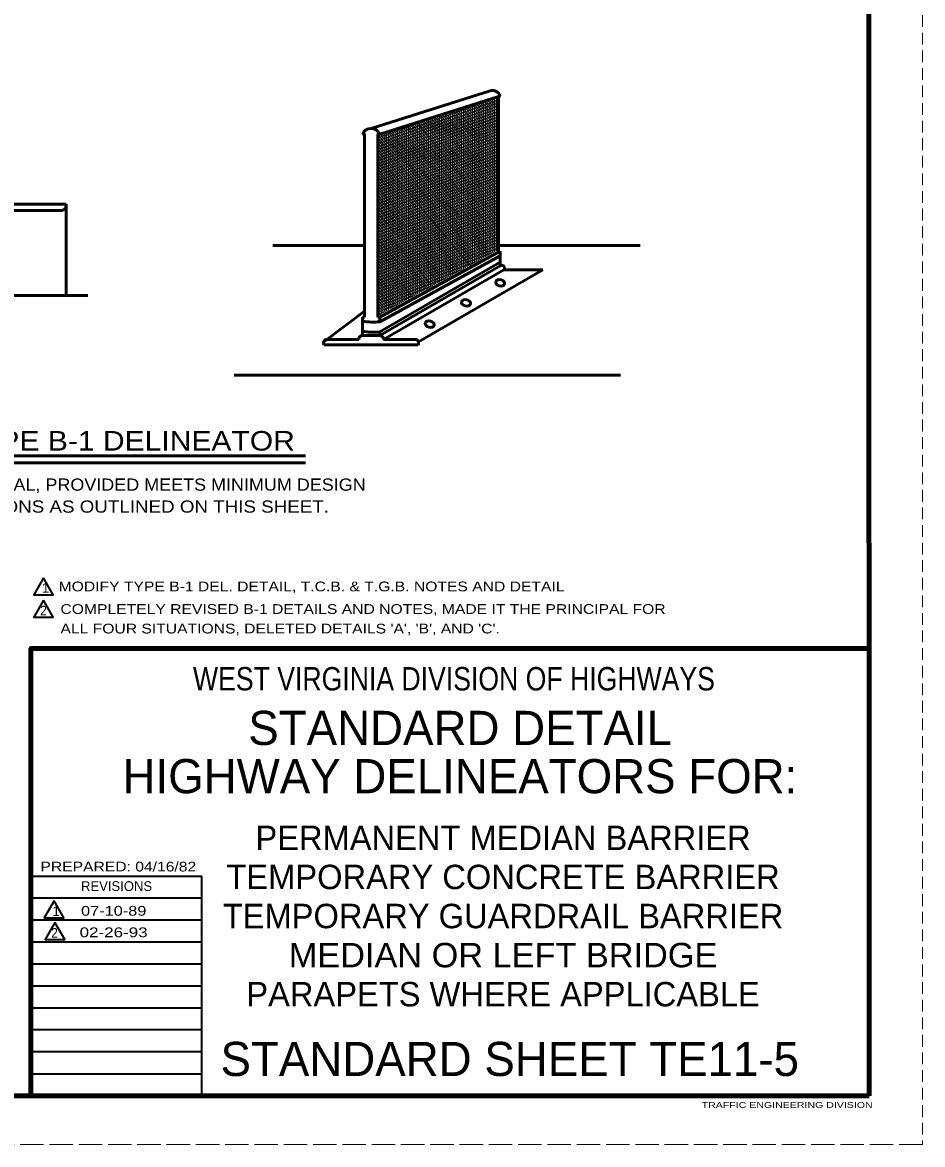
# Model space of a CAD drawing. Extents: x -60 to 620, y -42 to 398.
# Drawn here: x 435.5 to 619.8, y -41.8 to 188 of the extents above; entities that cross this region are included whole.
import ezdxf
from ezdxf.enums import TextEntityAlignment as Align

# ---------------------------------------------------------------- set-up
doc = ezdxf.new("R2010")
doc.units = 0
doc.header["$LTSCALE"] = 0.8
doc.linetypes.add('LONG_DASHED', pattern=[7.5, 6, -1.5])
doc.linetypes.add('MEDIUM_DASHED', pattern=[4.5, 3, -1.5])
doc.layers.add('1', color=7, linetype='Continuous', lineweight=35)
doc.layers.add('61', color=7, linetype='Continuous', lineweight=35)

msp = doc.modelspace()

# ---------------------------------------------------------------- linework, layer by layer
at = {"layer": '1', "linetype": 'MEDIUM_DASHED', "lineweight": 13}
msp.add_line((619.8045, 398.2688), (619.7845, -41.7512), dxfattribs=at)
at = {"layer": '1', "lineweight": 53}
for p, q in [((506.8685, 166.2969), (531.2212, 173.9919)), ((532.9795, 172.8494), (533.3371, 172.9623)), ((532.9795, 172.8494), (532.9795, 141.4507)), ((424.8831, 150.8207), (444.3847, 150.8207)), ((431.2068, 149.5082), (443.4472, 149.5082)), ((444.3847, 150.8207), (444.3847, 132.0707)), ((486.7143, 142.3509), (505.4851, 142.3509)), ((508.6268, 127.6544), (533.3086, 141.1544)), ((532.9795, 142.3509), (561.9874, 142.3509)), ((532.9795, 140.9744), (532.9795, 141.4507)), ((533.3086, 140.222), (533.3086, 141.1544)), ((508.6268, 123.9044), (533.3086, 138.1544)), ((509.3739, 123.089), (534.0557, 137.339)), ((516.5548, 122.6077), (542.0703, 137.339)), ((534.0557, 137.339), (542.0703, 137.339)), ((427.6029, 132.0707), (448.8847, 132.0707)), ((497.182, 122.6077), (505.4851, 128.8849)), ((505.1101, 127.6544), (505.4851, 127.6544)), ((505.1101, 126.7952), (505.1101, 127.6544)), ((505.1101, 124.7793), (505.1101, 126.7952)), ((505.1101, 124.7793), (505.1101, 126.7952)), ((508.2518, 127.6544), (508.2518, 127.9256)), ((508.6268, 127.6544), (508.2518, 127.6544)), ((508.6268, 126.722), (508.6268, 127.6544)), ((508.6268, 123.9044), (508.6268, 124.6573)), ((516.4989, 121.964), (497.2379, 121.964)), ((504.3629, 123.089), (497.6129, 123.089)), ((505.1101, 123.9044), (508.6268, 123.9044)), ((509.3739, 123.089), (516.1239, 123.089)), ((478.8432, 115.7483), (557.9643, 115.7483)), ((421.4774, 99.2887), (493.4133, 99.2887)), ((421.4774, 97.8201), (493.4133, 97.8201))]:
    msp.add_line(p, q, dxfattribs=at)
at = {"layer": '1', "lineweight": 13}
for p, q in [((531.3968, 140.5851), (531.3968, 172.3492)), ((532.9795, 170.5861), (531.4783, 172.375)), ((531.7718, 140.7902), (531.7718, 172.4677)), ((532.9795, 171.1694), (531.8653, 172.4973)), ((532.1468, 140.9952), (532.1468, 172.5863)), ((532.9795, 171.7528), (532.2523, 172.6195)), ((532.5218, 141.2004), (532.5218, 172.7047)), ((532.9795, 172.3363), (532.6392, 172.7418)), ((532.8968, 141.4055), (532.8968, 172.8232)), ((532.9795, 159.5015), (524.1266, 170.052)), ((524.2718, 136.6879), (524.2718, 170.0979)), ((532.9795, 160.0849), (524.5136, 170.1743)), ((524.6468, 136.8931), (524.6468, 170.2164)), ((532.9795, 160.6683), (524.9005, 170.2965)), ((525.0218, 137.0982), (525.0218, 170.3349)), ((532.9795, 161.2517), (525.2874, 170.4187)), ((525.3968, 137.3032), (525.3968, 170.4534)), ((532.9795, 161.8351), (525.6743, 170.5411)), ((525.7718, 137.5084), (525.7718, 170.5719)), ((532.9795, 162.4185), (526.0612, 170.6633)), ((526.1468, 137.7135), (526.1468, 170.6904)), ((532.9795, 163.0019), (526.4482, 170.7856)), ((526.5218, 137.9187), (526.5218, 170.8088)), ((532.9795, 163.5853), (526.8351, 170.9078)), ((526.8968, 138.1237), (526.8968, 170.9273)), ((532.9795, 164.1687), (527.2221, 171.0301)), ((527.2718, 138.3288), (527.2718, 171.0458)), ((532.9795, 164.7521), (527.609, 171.1524)), ((527.6468, 138.5339), (527.6468, 171.1643)), ((532.9795, 165.3355), (527.9959, 171.2747)), ((528.0218, 138.7391), (528.0218, 171.2828)), ((532.9795, 165.9189), (528.3828, 171.3969)), ((528.3968, 138.9442), (528.3968, 171.4013)), ((532.9795, 166.5023), (528.7698, 171.5192)), ((528.7718, 139.1492), (528.7718, 171.5198)), ((529.1468, 139.3544), (529.1468, 171.6383)), ((532.9795, 167.0857), (529.1567, 171.6414)), ((529.5218, 139.5595), (529.5218, 171.7567)), ((532.9795, 167.6691), (529.5437, 171.7637)), ((529.8968, 139.7647), (529.8968, 171.8752)), ((532.9795, 168.2524), (529.9306, 171.8859)), ((530.2718, 139.9697), (530.2718, 171.9938)), ((532.9795, 168.8359), (530.3176, 172.0082)), ((530.6468, 140.1748), (530.6468, 172.1122)), ((532.9795, 169.4193), (530.7045, 172.1304)), ((531.0218, 140.3799), (531.0218, 172.2308)), ((532.9795, 170.0027), (531.0914, 172.2527)), ((517.1468, 132.7908), (517.1468, 167.8466)), ((532.9795, 149.0004), (517.1617, 167.8512)), ((517.5218, 132.9959), (517.5218, 167.965)), ((532.9795, 149.5838), (517.5487, 167.9735)), ((517.8968, 133.2011), (517.8968, 168.0835)), ((532.9795, 150.1672), (517.9356, 168.0957)), ((518.2718, 133.4062), (518.2718, 168.202)), ((532.9795, 150.7506), (518.3226, 168.218)), ((518.6468, 133.6112), (518.6468, 168.3205)), ((532.9795, 151.3339), (518.7095, 168.3403)), ((519.0218, 133.8164), (519.0218, 168.439)), ((532.9795, 151.9174), (519.0964, 168.4626)), ((519.3968, 134.0215), (519.3968, 168.5575)), ((532.9795, 152.5007), (519.4833, 168.5848)), ((519.7718, 134.2267), (519.7718, 168.676)), ((532.9795, 153.0842), (519.8703, 168.7071)), ((520.1468, 134.4317), (520.1468, 168.7945)), ((532.9795, 153.6676), (520.2572, 168.8294)), ((520.5218, 134.6368), (520.5218, 168.9129)), ((532.9795, 154.2509), (520.6442, 168.9517)), ((520.8968, 134.8419), (520.8968, 169.0314)), ((532.9795, 154.8343), (521.0311, 169.0739)), ((521.2718, 135.0471), (521.2718, 169.1499)), ((532.9795, 155.4177), (521.4181, 169.1962)), ((521.6468, 135.2522), (521.6468, 169.2684)), ((532.9795, 156.0012), (521.805, 169.3184)), ((522.0218, 135.4572), (522.0218, 169.3869)), ((532.9795, 156.5845), (522.1919, 169.4407)), ((522.3968, 135.6624), (522.3968, 169.5054)), ((532.9795, 157.1679), (522.5788, 169.5629)), ((522.7718, 135.8675), (522.7718, 169.6239)), ((532.9795, 157.7513), (522.9658, 169.6852)), ((523.1468, 136.0727), (523.1468, 169.7424)), ((532.9795, 158.3347), (523.3528, 169.8074)), ((523.5218, 136.2777), (523.5218, 169.8609)), ((532.9795, 158.9182), (523.7397, 169.9297)), ((523.8968, 136.4828), (523.8968, 169.9794)), ((509.6468, 128.6887), (509.6468, 165.4767)), ((530.9465, 140.3387), (509.8099, 165.5282)), ((510.0218, 128.8937), (510.0218, 165.5952)), ((531.282, 140.5222), (510.1968, 165.6505)), ((510.3968, 129.0988), (510.3968, 165.7137)), ((531.6176, 140.7057), (510.5838, 165.7728)), ((510.7718, 129.3039), (510.7718, 165.8322)), ((531.9531, 140.8893), (510.9708, 165.895)), ((511.1468, 129.5091), (511.1468, 165.9507)), ((532.2886, 141.0728), (511.3577, 166.0172)), ((511.5218, 129.7142), (511.5218, 166.0692)), ((532.6241, 141.2563), (511.7446, 166.1396)), ((511.8968, 129.9193), (511.8968, 166.1877)), ((532.9597, 141.4398), (512.1316, 166.2618)), ((512.2718, 130.1244), (512.2718, 166.3062)), ((532.9795, 141.9997), (512.5185, 166.3841)), ((512.6468, 130.3295), (512.6468, 166.4247)), ((532.9795, 142.583), (512.9054, 166.5063)), ((513.0218, 130.5347), (513.0218, 166.5432)), ((532.9795, 143.1664), (513.2923, 166.6287)), ((513.3968, 130.7397), (513.3968, 166.6617)), ((532.9795, 143.7498), (513.6793, 166.7509)), ((513.7718, 130.9448), (513.7718, 166.7802)), ((532.9795, 144.3332), (514.0662, 166.8732)), ((514.1468, 131.1499), (514.1468, 166.8987)), ((532.9795, 144.9167), (514.4532, 166.9954)), ((514.5218, 131.3551), (514.5218, 167.0171)), ((532.9795, 145.5), (514.8401, 167.1177)), ((514.8968, 131.5602), (514.8968, 167.1356)), ((532.9795, 146.0834), (515.2271, 167.2399)), ((515.2718, 131.7653), (515.2718, 167.2541)), ((532.9795, 146.6668), (515.614, 167.3622)), ((515.6468, 131.9704), (515.6468, 167.3726)), ((532.9795, 147.2502), (516.0009, 167.4844)), ((516.0218, 132.1755), (516.0218, 167.4911)), ((532.9795, 147.8336), (516.3878, 167.6067)), ((516.3968, 132.3807), (516.3968, 167.6096)), ((516.7718, 132.5857), (516.7718, 167.7281)), ((532.9795, 148.417), (516.7748, 167.729)), ((529.6043, 139.6047), (508.2518, 165.0516)), ((529.2688, 139.4211), (508.2518, 164.4682)), ((528.9332, 139.2376), (508.2518, 163.8847)), ((528.5978, 139.0541), (508.2518, 163.3014)), ((508.5218, 128.0733), (508.5218, 165.1544)), ((529.9398, 139.7882), (508.6491, 165.1614)), ((508.8968, 128.2784), (508.8968, 165.2397)), ((530.2754, 139.9717), (509.0361, 165.2837)), ((509.2718, 128.4835), (509.2718, 165.3582)), ((530.6109, 140.1552), (509.423, 165.4059)), ((528.2622, 138.8705), (508.2518, 162.718)), ((527.9267, 138.687), (508.2518, 162.1346)), ((527.5911, 138.5034), (508.2518, 161.5512)), ((527.2556, 138.3199), (508.2518, 160.9678)), ((526.9201, 138.1364), (508.2518, 160.3844)), ((526.5846, 137.9529), (508.2518, 159.801)), ((526.249, 137.7694), (508.2518, 159.2177)), ((525.9135, 137.5858), (508.2518, 158.6342)), ((525.5779, 137.4023), (508.2518, 158.0508)), ((525.2424, 137.2188), (508.2518, 157.4674)), ((524.9068, 137.0352), (508.2518, 156.884)), ((524.5713, 136.8517), (508.2518, 156.3007)), ((524.2358, 136.6683), (508.2518, 155.7172)), ((523.9003, 136.4847), (508.2518, 155.1338)), ((523.5648, 136.3012), (508.2518, 154.5504)), ((523.2292, 136.1177), (508.2518, 153.967)), ((522.8937, 135.9342), (508.2518, 153.3837)), ((522.5581, 135.7507), (508.2518, 152.8003)), ((522.2226, 135.5671), (508.2518, 152.2168)), ((521.8871, 135.3836), (508.2518, 151.6334)), ((521.5516, 135.2), (508.2518, 151.0501)), ((521.216, 135.0165), (508.2518, 150.4667)), ((520.8805, 134.833), (508.2518, 149.8833)), ((520.5449, 134.6494), (508.2518, 149.2999)), ((520.2094, 134.4659), (508.2518, 148.7164)), ((519.8738, 134.2824), (508.2518, 148.1331)), ((519.5383, 134.0989), (508.2518, 147.5497)), ((519.2028, 133.9154), (508.2518, 146.9663)), ((518.8673, 133.7318), (508.2518, 146.3829)), ((518.5317, 133.5483), (508.2518, 145.7995)), ((518.1962, 133.3648), (508.2518, 145.2161)), ((517.8607, 133.1813), (508.2518, 144.6327)), ((517.5252, 132.9977), (508.2518, 144.0493)), ((517.1896, 132.8142), (508.2518, 143.4659)), ((516.8541, 132.6307), (508.2518, 142.8825)), ((516.5186, 132.4472), (508.2518, 142.2992)), ((516.1831, 132.2637), (508.2518, 141.7157)), ((515.8475, 132.0802), (508.2518, 141.1323)), ((515.5119, 131.8967), (508.2518, 140.5489)), ((515.1764, 131.7131), (508.2518, 139.9655)), ((514.8408, 131.5296), (508.2518, 139.3822)), ((514.5053, 131.346), (508.2518, 138.7987)), ((514.1698, 131.1625), (508.2518, 138.2153)), ((513.8343, 130.979), (508.2518, 137.6319)), ((513.4987, 130.7954), (508.2518, 137.0486)), ((513.1632, 130.6119), (508.2518, 136.4652)), ((512.8277, 130.4284), (508.2518, 135.8817)), ((512.4922, 130.2449), (508.2518, 135.2983)), ((512.1566, 130.0614), (508.2518, 134.7149)), ((511.8211, 129.8778), (508.2518, 134.1316)), ((511.4856, 129.6943), (508.2518, 133.5482)), ((511.1501, 129.5108), (508.2518, 132.9648)), ((510.8145, 129.3272), (508.2518, 132.3814)), ((510.479, 129.1437), (508.2518, 131.7979)), ((510.1434, 128.9602), (508.2518, 131.2146)), ((509.8079, 128.7767), (508.2518, 130.6312)), ((509.4723, 128.5932), (508.2518, 130.0478)), ((509.1368, 128.4097), (508.2518, 129.4644)), ((508.8013, 128.2262), (508.2518, 128.881)), ((508.4657, 128.0426), (508.2518, 128.2976))]:
    msp.add_line(p, q, dxfattribs=at)
at = {"layer": '1'}
for p, q in [((472.1845, 8.6687), (437.2045, 8.6687)), ((472.1845, 4.1688), (437.2045, 4.1688)), ((472.1845, -0.3312), (437.2045, -0.3312)), ((472.1845, -4.8512), (437.2045, -4.8512)), ((472.1845, -9.3312), (437.2045, -9.3312)), ((472.1845, -13.8112), (437.2045, -13.8112)), ((472.1845, -18.3113), (437.2045, -18.3113)), ((472.1845, -22.8112), (437.2045, -22.8112)), ((472.1845, -27.3313), (437.2045, -27.3313))]:
    msp.add_line(p, q, dxfattribs=at)
at = {"layer": '1', "lineweight": 53}
for points in [[(508.2518, 127.9256), (508.2518, 165.1544), (508.6268, 165.1544), (532.9795, 172.8493)], [(505.4851, 127.6544), (505.4851, 165.1544), (505.1101, 165.1544)], [(508.6268, 126.722), (533.3086, 140.222), (533.3086, 138.9073)], [(508.6268, 126.722), (533.3086, 140.222), (533.3086, 138.9073), (508.6268, 124.6573)], [(533.3086, 138.1544), (533.3086, 138.9073), (508.6268, 124.6573)], [(505.1101, 123.9044), (505.1101, 124.7793), (505.1101, 126.7952)]]:
    msp.add_lwpolyline(points, dxfattribs=at)
at = {"layer": '1'}
for points in [[(439.7777, 74.289), (437.7777, 70.8249), (441.7777, 70.8249)], [(439.7777, 69.6962), (437.7777, 66.2322), (441.7777, 66.2322)], [(441.9377, 8.1107), (439.9377, 4.6466), (443.9377, 4.6466)], [(442.1161, 3.7079), (440.1161, 0.2438), (444.1161, 0.2438)]]:
    msp.add_lwpolyline(points, close=True, dxfattribs=at)
at = {"layer": '1', "lineweight": 158}
msp.add_lwpolyline([(437.1845, -31.7712), (437.1845, 59.8087), (608.8445, 59.8087)], dxfattribs=at)
at = {"layer": '1'}
msp.add_lwpolyline([(472.1845, -31.8112), (472.1845, 13.1487), (437.2045, 13.1487)], dxfattribs=at)
at = {"layer": '1', "lineweight": 53}
for centre, radius, start, end in [((531.6615, 172.2078), 1.8376, 24.24274, 103.86313), ((506.8684, 164.3726), 1.9243, 23.97063, 156.02937), ((443.338, 150.5772), 1.0746, 275.83245, 13.09219), ((533.6356, 137.7041), 0.5565, 319.0044, 125.99342), ((507.1538, 140.4809), 13.8375, 261.50666, 276.11052), ((507.2552, 135.8687), 11.295, 259.05222, 276.97493), ((497.9536, 122.3504), 0.8133, 114.76219, 208.36791), ((505.1101, 123.1544), 0.75, 90, 184.99928), ((508.6268, 123.1544), 0.75, 355.00162, 90), ((515.7832, 122.3504), 0.8133, 331.63209, 65.23781)]:
    msp.add_arc(centre, radius, start, end, dxfattribs=at)
for centre in [(533.3008, 134.6782), (526.3062, 130.5891), (518.8573, 126.2274)]:
    msp.add_ellipse(centre, major_axis=(-0.8966, 0.2663), ratio=0.688779, dxfattribs=at)
at = {"layer": '61', "lineweight": 158}
for p, q in [((608.8245, 388.2688), (608.8445, -31.7712)), ((608.8445, -31.7712), (-30.2155, -31.7512))]:
    msp.add_line(p, q, dxfattribs=at)
at = {"layer": '61', "linetype": 'LONG_DASHED', "lineweight": 13}
msp.add_line((619.7845, -41.7512), (-60.2755, -41.7713), dxfattribs=at)

# ---------------------------------------------------------------- texts
at = {"layer": '1'}
for s, height, width, p in [('TYPE B-1 DELINEATOR', 4, 1.15, (457.07, 100.3326)), ('WEST VIRGINIA DIVISION OF HIGHWAYS', 4.795, 0.85, (523.8328, 51.2087)), ('07-10-89', 2, 1.25, (454.1538, 5.0888)), ('02-26-93', 2, 1.3, (454.1337, 0.6887)), ('MEDIAN OR LEFT BRIDGE', 5, 1.05, (533.8906, -5.474))]:
    msp.add_text(s, height=height, dxfattribs=dict(at, width=width)).set_placement(p, align=Align.CENTER)
for s, height, width, p in [('SHAPE NOMINAL, PROVIDED MEETS MINIMUM DESIGN', 2.5, 1.1, (407.8817, 92.1167)), ('SPECIFICATIONS AS OUTLINED ON THIS SHEET.', 2.5, 1.15, (407.8817, 87.6167)), ('MODIFY TYPE B-1 DEL. DETAIL, T.C.B. & T.G.B. NOTES AND DETAIL', 2, 1.2, (442.8697, 71.5089)), ('2', 2, 0.9, (439.101, 66.582)), ('COMPLETELY REVISED B-1 DETAILS AND NOTES, MADE IT THE PRINCIPAL FOR', 2, 1.2, (443.2442, 66.8845)), ("ALL FOUR SITUATIONS, DELETED DETAILS 'A', 'B', AND 'C'.", 2, 1.2, (443.2442, 62.8845)), ('PREPARED: 04/16/82', 1.998, 1.2, (439.1445, 14.1487)), ('2', 2, 0.9, (441.3602, 0.5743)), ('TRAFFIC ENGINEERING DIVISION', 1.2, 1.35, (574.5645, -34.2713))]:
    msp.add_text(s, height=height, dxfattribs=dict(at, width=width)).set_placement(p)
for s, height, p in [('1', 2, (439.4428, 71.2108)), ('REVISIONS', 1.998, (447.4645, 10.1487)), ('1', 2, (441.5981, 5.0365)), ('STANDARD SHEET TE11-5', 6.993, (476.0245, -27.7312))]:
    msp.add_text(s, height=height, dxfattribs=at).set_placement(p)
for s, height, p in [('STANDARD DETAIL', 6.993, (525.1015, 40.0487)), ('HIGHWAY DELINEATORS FOR:', 6.993, (525.0548, 30.1665)), ('PERMANENT MEDIAN BARRIER', 5, (533.8906, 18.526)), ('TEMPORARY CONCRETE BARRIER', 5, (533.8905, 10.526)), ('TEMPORARY GUARDRAIL BARRIER', 5, (533.8906, 2.526)), ('PARAPETS WHERE APPLICABLE', 5, (533.8905, -13.474))]:
    msp.add_text(s, height=height, dxfattribs=at).set_placement(p, align=Align.CENTER)

doc.saveas('drawing.dxf')
